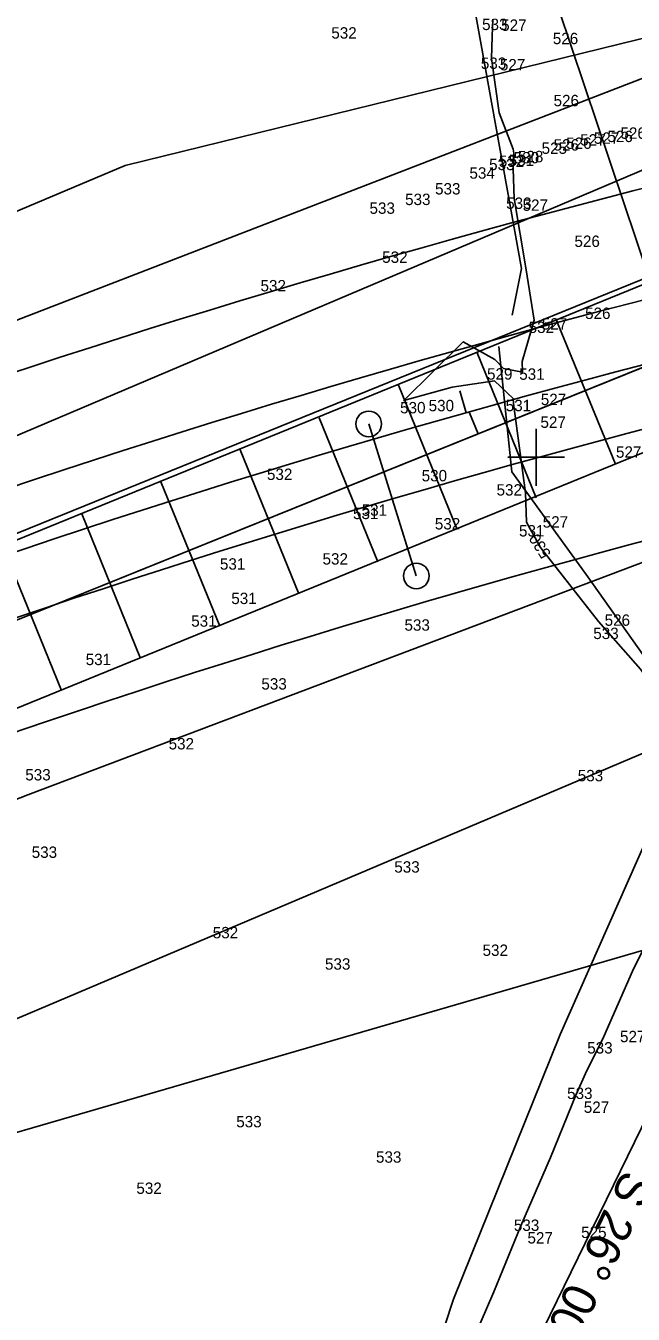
# Model space of a CAD drawing. Extents: x 1787461 to 1970323, y 938412 to 1118748.
# Drawn here: x 1967710 to 1967816.7, y 1117714.7 to 1117941.2 of the extents above; entities that cross this region are included whole.
import ezdxf

# ---------------------------------------------------------------- set-up
doc = ezdxf.new("R2010")
doc.units = 0
for name, color, linetype in [('Default', 7, 'Continuous'), ('HHA ADDITIONAL XSs', 7, 'Continuous'), ('Level 1', 7, 'Continuous'), ('Level 19', 7, 'Continuous'), ('RD_EX_Bridge', 7, 'Continuous'), ('RD_EX_DV_Prop', 7, 'Continuous'), ('RD_EX_H2O', 7, 'Continuous'), ('RD_EX_Misc', 7, 'Continuous'), ('RD_EX_VEG', 7, 'Continuous'), ('RD_HC_CL', 7, 'Continuous'), ('RD_HC_CL_Rel', 7, 'Continuous'), ('RD_HC_Data', 7, 'Continuous'), ('RD_HC_Data_Tic', 7, 'Continuous'), ('RD_HC_Data_Tic_Rel', 7, 'Continuous'), ('RD_PD_Final_TrvlWay', 7, 'Continuous')]:
    doc.layers.add(name, color=color, linetype=linetype)

msp = doc.modelspace()

# ---------------------------------------------------------------- linework, layer by layer
at = {"layer": 'Default'}
for points in [[(1967792.01, 1117942.36), (1967791.9, 1117939.31), (1967791.78, 1117935.46), (1967793.16, 1117925.91), (1967795.63, 1117919.51), (1967795.74, 1117918.79), (1967795.59, 1117916.05), (1967795.76, 1117910.85), (1967797.85, 1117898.67), (1967799.28, 1117889.44), (1967797.21, 1117882.17), (1967797.23, 1117880.3), (1967793.9, 1117880.98), (1967792.38, 1117882.53), (1967786.85, 1117885.65), (1967776.39, 1117875.32), (1967784.9, 1117877.68), (1967792.33, 1117878.78), (1967795.61, 1117875.68), (1967795.64, 1117874.81), (1967797.76, 1117859.12), (1967797.94, 1117853.92), (1967800.4, 1117849.5), (1967810.59, 1117836.47), (1967817.97, 1117828.1)], [(1967792.01, 1117942.36), (1967791.9, 1117939.31), (1967791.78, 1117935.46), (1967793.16, 1117925.91), (1967795.63, 1117919.51), (1967795.74, 1117918.79), (1967795.59, 1117916.05), (1967795.76, 1117910.85), (1967797.85, 1117898.67), (1967799.28, 1117889.44), (1967797.21, 1117882.17), (1967797.23, 1117880.3), (1967793.9, 1117880.98), (1967792.38, 1117882.53), (1967786.85, 1117885.65), (1967776.39, 1117875.32), (1967784.9, 1117877.68), (1967792.33, 1117878.78), (1967795.61, 1117875.68), (1967795.64, 1117874.81), (1967797.76, 1117859.12), (1967797.94, 1117853.92), (1967798.65, 1117852.64)], [(1967792.01, 1117942.36), (1967791.9, 1117939.31), (1967791.78, 1117935.46), (1967793.16, 1117925.91), (1967795.63, 1117919.51), (1967795.74, 1117918.79), (1967795.59, 1117916.05), (1967795.76, 1117910.85), (1967797.85, 1117898.67), (1967799.28, 1117889.44), (1967797.21, 1117882.17), (1967797.23, 1117880.3), (1967793.9, 1117880.98), (1967792.38, 1117882.53), (1967786.85, 1117885.65), (1967776.39, 1117875.32), (1967784.9, 1117877.68), (1967792.33, 1117878.78), (1967795.61, 1117875.68), (1967795.64, 1117874.81), (1967797.76, 1117859.12), (1967797.94, 1117853.92), (1967798.65, 1117852.64)], [(1967792.01, 1117942.36), (1967791.9, 1117939.31), (1967791.78, 1117935.46), (1967793.16, 1117925.91), (1967795.63, 1117919.51), (1967795.74, 1117918.79), (1967795.59, 1117916.05), (1967795.76, 1117910.85), (1967797.85, 1117898.67), (1967799.28, 1117889.44), (1967797.21, 1117882.17), (1967797.23, 1117880.3), (1967793.9, 1117880.98), (1967792.38, 1117882.53), (1967786.85, 1117885.65), (1967776.39, 1117875.32), (1967784.9, 1117877.68), (1967792.33, 1117878.78), (1967795.61, 1117875.68), (1967795.64, 1117874.81), (1967797.76, 1117859.12), (1967797.94, 1117853.92), (1967798.65, 1117852.64)], [(1967792.01, 1117942.36), (1967791.9, 1117939.31), (1967791.78, 1117935.46), (1967793.16, 1117925.91), (1967795.63, 1117919.51), (1967795.74, 1117918.79), (1967795.59, 1117916.05), (1967795.76, 1117910.85), (1967797.85, 1117898.67), (1967799.28, 1117889.44), (1967797.21, 1117882.17), (1967797.23, 1117880.3), (1967793.9, 1117880.98), (1967792.38, 1117882.53), (1967786.85, 1117885.65), (1967776.39, 1117875.32), (1967784.9, 1117877.68), (1967792.33, 1117878.78), (1967795.61, 1117875.68), (1967795.64, 1117874.81), (1967797.76, 1117859.12), (1967797.94, 1117853.92), (1967798.65, 1117852.64)], [(1967792.01, 1117942.36), (1967791.9, 1117939.31), (1967791.78, 1117935.46), (1967793.16, 1117925.91), (1967795.63, 1117919.51), (1967795.74, 1117918.79), (1967795.59, 1117916.05), (1967795.76, 1117910.85), (1967797.85, 1117898.67), (1967799.28, 1117889.44), (1967797.21, 1117882.17), (1967797.23, 1117880.3), (1967793.9, 1117880.98), (1967792.38, 1117882.53), (1967786.85, 1117885.65), (1967776.39, 1117875.32), (1967784.9, 1117877.68), (1967792.33, 1117878.78), (1967795.61, 1117875.68), (1967795.64, 1117874.81), (1967797.76, 1117859.12), (1967797.94, 1117853.92), (1967798.65, 1117852.64)], [(1967792.01, 1117942.36), (1967791.9, 1117939.31), (1967791.78, 1117935.46), (1967793.16, 1117925.91), (1967795.63, 1117919.51), (1967795.74, 1117918.79), (1967795.59, 1117916.05), (1967795.76, 1117910.85), (1967797.85, 1117898.67), (1967799.28, 1117889.44), (1967797.21, 1117882.17), (1967797.23, 1117880.3), (1967793.9, 1117880.98), (1967792.38, 1117882.53), (1967786.85, 1117885.65), (1967776.39, 1117875.32), (1967784.9, 1117877.68), (1967792.33, 1117878.78), (1967795.61, 1117875.68), (1967795.64, 1117874.81), (1967797.76, 1117859.12), (1967797.94, 1117853.92), (1967798.65, 1117852.64)], [(1967801.88, 1117847.61), (1967810.59, 1117836.47), (1967817.97, 1117828.1), (1967825.91, 1117816.75), (1967828.59, 1117812.93), (1967832.36, 1117808.61), (1967834.19, 1117807.04), (1967834.93, 1117806.3), (1967834.88, 1117806.26), (1967831.61, 1117800.38), (1967827.33, 1117795.88), (1967821.98, 1117786.05), (1967816.55, 1117775), (1967811.53, 1117763.56), (1967808.3, 1117757.03), (1967806.64, 1117753.26), (1967802.17, 1117742.25), (1967796.95, 1117730.25), (1967792.24, 1117718.65), (1967787.4, 1117707.51)], [(1967801.88, 1117847.61), (1967810.59, 1117836.47), (1967817.97, 1117828.1), (1967825.91, 1117816.75), (1967828.59, 1117812.93), (1967832.36, 1117808.61), (1967834.19, 1117807.04), (1967834.93, 1117806.3), (1967834.88, 1117806.26), (1967831.61, 1117800.38), (1967827.33, 1117795.88), (1967821.98, 1117786.05), (1967816.55, 1117775), (1967811.53, 1117763.56), (1967808.3, 1117757.03), (1967806.64, 1117753.26), (1967802.17, 1117742.25), (1967796.95, 1117730.25), (1967792.24, 1117718.65), (1967787.4, 1117707.51)], [(1967801.88, 1117847.61), (1967810.59, 1117836.47), (1967817.97, 1117828.1), (1967825.91, 1117816.75), (1967828.59, 1117812.93), (1967832.36, 1117808.61), (1967834.19, 1117807.04), (1967834.93, 1117806.3), (1967834.88, 1117806.26), (1967831.61, 1117800.38), (1967827.33, 1117795.88), (1967821.98, 1117786.05), (1967816.55, 1117775), (1967811.53, 1117763.56), (1967808.3, 1117757.03), (1967806.64, 1117753.26), (1967802.17, 1117742.25), (1967796.95, 1117730.25), (1967792.24, 1117718.65), (1967787.4, 1117707.51)], [(1967801.88, 1117847.61), (1967810.59, 1117836.47), (1967817.97, 1117828.1), (1967825.91, 1117816.75), (1967828.59, 1117812.93), (1967832.36, 1117808.61), (1967834.19, 1117807.04), (1967834.93, 1117806.3), (1967834.88, 1117806.26), (1967831.61, 1117800.38), (1967827.33, 1117795.88), (1967821.98, 1117786.05), (1967816.55, 1117775), (1967811.53, 1117763.56), (1967808.3, 1117757.03), (1967806.64, 1117753.26), (1967802.17, 1117742.25), (1967796.95, 1117730.25), (1967792.24, 1117718.65), (1967787.4, 1117707.51)], [(1967801.88, 1117847.61), (1967810.59, 1117836.47), (1967817.97, 1117828.1), (1967825.91, 1117816.75), (1967828.59, 1117812.93), (1967832.36, 1117808.61), (1967834.19, 1117807.04), (1967834.93, 1117806.3), (1967834.88, 1117806.26), (1967831.61, 1117800.38), (1967827.33, 1117795.88), (1967821.98, 1117786.05), (1967816.55, 1117775), (1967811.53, 1117763.56), (1967808.3, 1117757.03), (1967806.64, 1117753.26), (1967802.17, 1117742.25), (1967796.95, 1117730.25), (1967792.24, 1117718.65), (1967787.4, 1117707.51)], [(1967801.88, 1117847.61), (1967810.59, 1117836.47), (1967817.97, 1117828.1), (1967825.91, 1117816.75), (1967828.59, 1117812.93), (1967832.36, 1117808.61), (1967834.19, 1117807.04), (1967834.93, 1117806.3), (1967834.88, 1117806.26), (1967831.61, 1117800.38), (1967827.33, 1117795.88), (1967821.98, 1117786.05), (1967816.55, 1117775), (1967811.53, 1117763.56), (1967808.3, 1117757.03), (1967806.64, 1117753.26), (1967802.17, 1117742.25), (1967796.95, 1117730.25), (1967792.24, 1117718.65), (1967787.4, 1117707.51)], [(1967821.98, 1117786.05), (1967816.55, 1117775), (1967811.53, 1117763.56), (1967808.3, 1117757.03), (1967806.64, 1117753.26), (1967802.17, 1117742.25), (1967796.95, 1117730.25), (1967792.24, 1117718.65), (1967787.4, 1117707.51)]]:
    msp.add_lwpolyline(points, dxfattribs=at)
at = {"layer": 'HHA ADDITIONAL XSs'}
for points in [[(1969266.55, 1117963.61), (1967907.56, 1117966.55), (1967403.98, 1117771.66), (1967075.57, 1117641.84)], [(1969308.89, 1117819.66), (1967912.94, 1117853.44), (1967442.55, 1117653.93), (1967107.32, 1117508.48)]]:
    msp.add_lwpolyline(points, dxfattribs=at)
for radius in [1667.02, 1607.02]:
    msp.add_arc((1968231.34, 1116297.54), radius, 87.72663, 111.99584, dxfattribs=at)
at = {"layer": 'Level 1'}
for points in [[(1968647.29, 1117975.82), (1967967.92, 1117975.82), (1967727.47, 1117916.63), (1966985.13, 1117603.01)], [(1968654.57, 1117840.68), (1968058.24, 1117848.48), (1967686.38, 1117740.3), (1966964.76, 1117453.35)]]:
    msp.add_lwpolyline(points, dxfattribs=at)
at = {"layer": 'Level 19'}
msp.add_line((1967778.6, 1117844.49), (1967770.24, 1117871.21), dxfattribs=at)
for centre in [(1967770.24, 1117871.21), (1967778.6, 1117844.49)]:
    msp.add_circle(centre, 2.25, dxfattribs=at)
at = {"layer": 'RD_EX_Bridge'}
msp.add_lwpolyline([(1967691.93, 1117844.09), (1967872.42, 1117917.74), (1967882.76, 1117892.41), (1967702.27, 1117818.76), (1967691.93, 1117844.09)], dxfattribs=at)
at = {"layer": 'RD_EX_DV_Prop'}
for p, q in [((1967803.58, 1117944.23), (1967823.97, 1117883.41)), ((1967696.84, 1117832.06), (1967823.97, 1117883.41)), ((1967848.59, 1117809.96), (1967728.08, 1117563.01))]:
    msp.add_line(p, q, dxfattribs=at)
at = {"layer": 'RD_EX_H2O'}
for points in [[(1967847.31, 1118356.81), (1967879.15, 1118347.14), (1967885.7, 1118340.94), (1967895.17, 1118292.21), (1967905.1, 1118241.75), (1967913.15, 1118203.17), (1967903.06, 1118190.95), (1967846.3, 1118148.6), (1967822.76, 1118102.41), (1967798.93, 1118056.05), (1967790.6, 1118001.77), (1967788.7, 1117944.97), (1967797.09, 1117898.55), (1967795.44, 1117890.32)], [(1967793.07, 1117884.81), (1967795.4, 1117862.79), (1967808.44, 1117844.76), (1967827.6, 1117817.64), (1967803.85, 1117763.92), (1967785.1, 1117717.4), (1967778.96, 1117698.7), (1967761.45, 1117660.55), (1967735.16, 1117625.66), (1967726.1, 1117620.57), (1967713.81, 1117582.71), (1967729.78, 1117524.09), (1967774.63, 1117477.47), (1967792.06, 1117468.24), (1967815.16, 1117463.54)]]:
    msp.add_lwpolyline(points, dxfattribs=at)
at = {"layer": 'RD_EX_Misc'}
for p, q in [((1967691.12, 1117844.93), (1967873.24, 1117918.94)), ((1967803.19, 1117889.39), (1967813.59, 1117864.13)), ((1967789.31, 1117883.69), (1967799.66, 1117858.24)), ((1967775.45, 1117878.01), (1967785.76, 1117852.68)), ((1967761.53, 1117872.31), (1967771.83, 1117846.98)), ((1967799.65, 1117860.35), (1967799.65, 1117870.35)), ((1967747.64, 1117866.64), (1967757.96, 1117841.32)), ((1967794.65, 1117865.35), (1967804.65, 1117865.35)), ((1967733.75, 1117861.02), (1967744.1, 1117835.68)), ((1967719.86, 1117855.42), (1967730.16, 1117830.01)), ((1967705.98, 1117849.73), (1967716.27, 1117824.34))]:
    msp.add_line(p, q, dxfattribs=at)
at = {"layer": 'RD_EX_VEG'}
for points in [[(1967420.8, 1117819.08), (1967452.15, 1117758.28), (1967558.57, 1117805.53), (1967843.24, 1117926.43), (1967916.63, 1117956.61), (1968008.44, 1117968.2), (1968060.25, 1117967.44), (1968104.58, 1117972.69), (1968157.63, 1117966.15), (1968211.15, 1117963.44), (1968421.93, 1117955.99), (1968535.19, 1117951.62)], [(1967302.31, 1117610.37), (1967337.76, 1117649.58), (1967352.05, 1117663.92), (1967393.53, 1117676.59), (1967483.38, 1117717.02), (1967710.35, 1117806.03), (1967888.86, 1117873.57), (1967928.06, 1117882.04), (1967957.92, 1117887.35), (1967975.7, 1117893.86), (1968013.09, 1117903.71), (1968102.91, 1117899.22), (1968154.08, 1117904.84), (1968208.62, 1117905.24), (1968319.32, 1117902.87), (1968421.81, 1117901.58), (1968527.92, 1117886.31)]]:
    msp.add_lwpolyline(points, dxfattribs=at)
at = {"layer": 'RD_HC_CL'}
for p, q in [((1967803.58, 1117944.23), (1967848.59, 1117809.96)), ((1966769.51, 1117457.48), (1967848.24, 1117893.22)), ((1967848.59, 1117809.96), (1967728.08, 1117563.01))]:
    msp.add_line(p, q, dxfattribs=at)
at = {"layer": 'RD_HC_CL_Rel'}
msp.add_arc((1968231.34, 1116297.54), 1637.02, 87.72663, 111.99584, dxfattribs=at)
at = {"layer": 'RD_HC_Data_Tic'}
msp.add_line((1967789.44, 1117869.47), (1967787.95, 1117873.18), dxfattribs=at)
at = {"layer": 'RD_HC_Data_Tic_Rel'}
msp.add_line((1967787.34, 1117873.19), (1967786.25, 1117877.04), dxfattribs=at)
at = {"layer": 'RD_PD_Final_TrvlWay'}
for radius in [1648.02, 1626.02]:
    msp.add_arc((1968231.34, 1116297.54), radius, 87.72663, 111.99584, dxfattribs=at)

# ---------------------------------------------------------------- texts
at = {"layer": 'Default'}
for s, p in [('533', (1967790.15, 1117940.44)), ('527', (1967793.5, 1117940.3)), ('532', (1967763.67, 1117938.94)), ('526', (1967802.57, 1117937.96)), ('533', (1967789.93, 1117933.61)), ('527', (1967793.27, 1117933.35)), ('526', (1967802.7, 1117927.05)), ('526', (1967804.91, 1117919.55)), ('527', (1967807.38, 1117920.14)), ('527', (1967809.77, 1117920.45)), ('526', (1967812.16, 1117920.75)), ('526', (1967814.45, 1117921.33)), ('528', (1967796.44, 1117917.21)), ('525', (1967800.6, 1117918.68)), ('526', (1967802.71, 1117919.26)), ('533', (1967791.38, 1117915.82)), ('532', (1967793.08, 1117916.39)), ('531', (1967794.82, 1117916.55)), ('530', (1967795.7, 1117917.01)), ('534', (1967787.93, 1117914.32)), ('533', (1967781.89, 1117911.54)), ('533', (1967770.38, 1117908.14)), ('533', (1967776.63, 1117909.68)), ('533', (1967794.37, 1117909.01)), ('527', (1967797.26, 1117908.67)), ('526', (1967806.37, 1117902.32)), ('532', (1967772.6, 1117899.52)), ('532', (1967751.24, 1117894.51)), ('527', (1967800.64, 1117887.8)), ('526', (1967808.24, 1117889.66)), ('532', (1967798.32, 1117887.19)), ('529', (1967791.02, 1117879)), ('531', (1967796.67, 1117878.97)), ('527', (1967800.46, 1117874.52)), ('530', (1967775.75, 1117873.07)), ('530', (1967780.76, 1117873.44)), ('531', (1967794.3, 1117873.45)), ('527', (1967800.4, 1117870.52)), ('527', (1967813.66, 1117865.27)), ('532', (1967752.37, 1117861.36)), ('530', (1967779.54, 1117861.12)), ('532', (1967792.69, 1117858.62)), ('531', (1967767.48, 1117854.48)), ('531', (1967769.01, 1117855.07)), ('532', (1967781.85, 1117852.66)), ('531', (1967796.63, 1117851.43)), ('527', (1967800.8, 1117852.99)), ('531', (1967744.11, 1117845.6)), ('532', (1967762.13, 1117846.49)), ('531', (1967746.11, 1117839.55)), ('531', (1967739.07, 1117835.57)), ('526', (1967811.67, 1117835.73)), ('533', (1967776.52, 1117834.87)), ('533', (1967809.67, 1117833.4)), ('531', (1967720.54, 1117828.82)), ('533', (1967751.39, 1117824.52)), ('532', (1967735.1, 1117814)), ('533', (1967709.93, 1117808.55)), ('533', (1967806.95, 1117808.4)), ('533', (1967711.06, 1117794.94)), ('533', (1967774.73, 1117792.35)), ('532', (1967742.85, 1117780.8)), ('532', (1967790.23, 1117777.71)), ('533', (1967762.56, 1117775.29)), ('527', (1967814.37, 1117762.54)), ('533', (1967808.61, 1117760.55)), ('533', (1967805.08, 1117752.56)), ('527', (1967808.01, 1117750.12)), ('533', (1967746.98, 1117747.58)), ('533', (1967771.52, 1117741.36)), ('532', (1967729.44, 1117735.88)), ('533', (1967795.73, 1117729.37)), ('527', (1967798.12, 1117727.16)), ('525', (1967807.55, 1117728.13))]:
    msp.add_text(s, height=2, dxfattribs=at).set_placement(p)
msp.add_text('530', height=2, rotation=122.6765, dxfattribs=at).set_placement((1967802.34, 1117848.39))
msp.add_text('530', height=2, rotation=122.6765, dxfattribs=at).set_placement((1967802.34, 1117848.39))
msp.add_text('530', height=2, rotation=122.6765, dxfattribs=at).set_placement((1967802.34, 1117848.39))
msp.add_text('530', height=2, rotation=122.6765, dxfattribs=at).set_placement((1967802.34, 1117848.39))
msp.add_text('530', height=2, rotation=122.6765, dxfattribs=at).set_placement((1967802.34, 1117848.39))
msp.add_text('530', height=2, rotation=122.6765, dxfattribs=at).set_placement((1967802.34, 1117848.39))
at = {"layer": 'RD_HC_Data'}
msp.add_text('S 26%%d 00\' 44" W', height=6, rotation=243.9877, dxfattribs=at).set_placement((1967815.06, 1117740.34))

doc.saveas('drawing.dxf')
